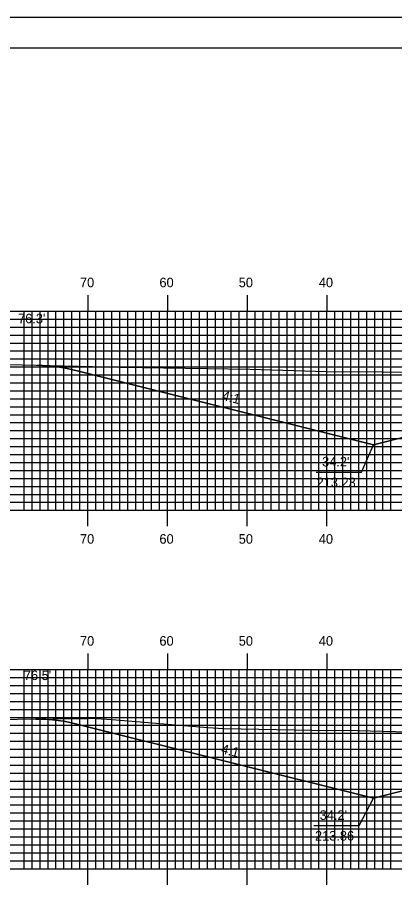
# Model space of a CAD drawing. Extents: x 1820424 to 1820768, y 442591 to 442811.
# Drawn here: x 1820511.4 to 1820558.7, y 442701.2 to 442810.5 of the extents above; entities that cross this region are included whole.
import ezdxf

# ---------------------------------------------------------------- set-up
doc = ezdxf.new("R2010")
doc.units = 0
for name, color, linetype in [('ANNOTATION', 7, 'Continuous'), ('BORDER', 7, 'Continuous'), ('D_Roadway_Centerline', 7, 'Continuous'), ('D_Roadway_SlopeLines', 7, 'Continuous'), ('D_Text_Standard', 7, 'Continuous'), ('H_V ANNOTATION', 7, 'Continuous'), ('MAJOR', 7, 'Continuous'), ('MINOR', 7, 'Continuous'), ('PLOT BOUNDARY', 7, 'Continuous'), ('S_Roadway_Centerline', 7, 'Continuous')]:
    doc.layers.add(name, color=color, linetype=linetype)

msp = doc.modelspace()

# ---------------------------------------------------------------- linework, layer by layer
at = {"layer": 'ANNOTATION'}
for points in [[(1820548.86, 442753.44), (1820554.55, 442753.44), (1820556.03, 442756.9)], [(1820548.55, 442709.08), (1820554.24, 442709.08), (1820556.03, 442712.52)]]:
    msp.add_lwpolyline(points, dxfattribs=at)
at = {"layer": 'BORDER'}
msp.add_lwpolyline([(1820440.6, 442596.67), (1820760.6, 442596.67), (1820760.6, 442806.67), (1820440.6, 442806.67)], close=True, dxfattribs=at)
at = {"layer": 'D_Roadway_Centerline'}
for points in [[(1820513.87, 442766.87), (1820515.12, 442766.81), (1820516.37, 442766.67), (1820517.62, 442766.46), (1820518.87, 442766.19), (1820556.03, 442756.9), (1820560.03, 442757.9), (1820570.2, 442760.44), (1820578.2, 442760.76), (1820590.2, 442761), (1820602.2, 442760.76), (1820612.2, 442760.36), (1820622.2, 442757.86), (1820626.2, 442756.86), (1820654.98, 442764.06), (1820656.23, 442764.33), (1820657.48, 442764.52), (1820658.73, 442764.63), (1820659.98, 442764.66)], [(1820513.66, 442722.46), (1820514.91, 442722.44), (1820516.16, 442722.33), (1820517.41, 442722.14), (1820518.66, 442721.87), (1820556.03, 442712.52), (1820560.03, 442713.52), (1820570.2, 442716.07), (1820578.2, 442716.39), (1820590.2, 442716.63), (1820602.2, 442716.39), (1820612.2, 442715.99), (1820622.2, 442713.49), (1820626.2, 442712.49), (1820652.27, 442719), (1820653.52, 442719.27), (1820654.77, 442719.47), (1820656.02, 442719.58), (1820657.27, 442719.62)]]:
    msp.add_lwpolyline(points, dxfattribs=at)
at = {"layer": 'D_Roadway_SlopeLines'}
for points in [[(1820556.03, 442756.9), (1820518.87, 442766.19), (1820517.62, 442766.46), (1820516.37, 442766.67), (1820515.12, 442766.81), (1820513.87, 442766.87)], [(1820570.2, 442760.44), (1820556.03, 442756.9)], [(1820556.03, 442712.52), (1820518.66, 442721.87), (1820517.41, 442722.14), (1820516.16, 442722.33), (1820514.91, 442722.44), (1820513.66, 442722.46)], [(1820570.2, 442716.07), (1820556.03, 442712.52)]]:
    msp.add_lwpolyline(points, dxfattribs=at)
at = {"layer": 'MAJOR'}
for p, q in [((1820520.2, 442775.67), (1820520.2, 442773.67)), ((1820530.2, 442775.67), (1820530.2, 442773.67)), ((1820540.2, 442775.67), (1820540.2, 442773.67)), ((1820550.2, 442775.67), (1820550.2, 442773.67)), ((1820450.2, 442773.67), (1820730.2, 442773.67)), ((1820450.2, 442773.67), (1820730.2, 442773.67)), ((1820520.2, 442748.67), (1820520.2, 442773.67)), ((1820530.2, 442748.67), (1820530.2, 442773.67)), ((1820540.2, 442748.67), (1820540.2, 442773.67)), ((1820550.2, 442748.67), (1820550.2, 442773.67)), ((1820450.2, 442768.67), (1820730.2, 442768.67)), ((1820450.2, 442763.67), (1820730.2, 442763.67)), ((1820450.2, 442758.67), (1820730.2, 442758.67)), ((1820450.2, 442753.67), (1820730.2, 442753.67)), ((1820450.2, 442748.67), (1820730.2, 442748.67)), ((1820450.2, 442748.67), (1820730.2, 442748.67)), ((1820520.2, 442746.66), (1820520.2, 442748.67)), ((1820530.2, 442746.66), (1820530.2, 442748.67)), ((1820540.2, 442746.66), (1820540.2, 442748.67)), ((1820550.2, 442746.66), (1820550.2, 442748.67)), ((1820520.2, 442730.67), (1820520.2, 442728.67)), ((1820530.2, 442730.67), (1820530.2, 442728.67)), ((1820540.2, 442730.67), (1820540.2, 442728.67)), ((1820550.2, 442730.67), (1820550.2, 442728.67)), ((1820450.2, 442728.67), (1820730.2, 442728.67)), ((1820450.2, 442728.67), (1820730.2, 442728.67)), ((1820520.2, 442703.67), (1820520.2, 442728.67)), ((1820530.2, 442703.67), (1820530.2, 442728.67)), ((1820540.2, 442703.67), (1820540.2, 442728.67)), ((1820550.2, 442703.67), (1820550.2, 442728.67)), ((1820450.2, 442723.67), (1820730.2, 442723.67)), ((1820450.2, 442718.67), (1820730.2, 442718.67)), ((1820450.2, 442713.67), (1820730.2, 442713.67)), ((1820450.2, 442708.67), (1820730.2, 442708.67)), ((1820450.2, 442703.67), (1820730.2, 442703.67)), ((1820450.2, 442703.67), (1820730.2, 442703.67)), ((1820520.2, 442701.66), (1820520.2, 442703.67)), ((1820530.2, 442701.66), (1820530.2, 442703.67)), ((1820540.2, 442701.66), (1820540.2, 442703.67)), ((1820550.2, 442701.66), (1820550.2, 442703.67))]:
    msp.add_line(p, q, dxfattribs=at)
at = {"layer": 'MINOR'}
for p, q in [((1820512.2, 442748.67), (1820512.2, 442773.67)), ((1820513.2, 442748.67), (1820513.2, 442773.67)), ((1820514.2, 442748.67), (1820514.2, 442773.67)), ((1820515.2, 442748.67), (1820515.2, 442773.67)), ((1820516.2, 442748.67), (1820516.2, 442773.67)), ((1820517.2, 442748.67), (1820517.2, 442773.67)), ((1820518.2, 442748.67), (1820518.2, 442773.67)), ((1820519.2, 442748.67), (1820519.2, 442773.67)), ((1820521.2, 442748.67), (1820521.2, 442773.67)), ((1820522.2, 442748.67), (1820522.2, 442773.67)), ((1820523.2, 442748.67), (1820523.2, 442773.67)), ((1820524.2, 442748.67), (1820524.2, 442773.67)), ((1820525.2, 442748.67), (1820525.2, 442773.67)), ((1820526.2, 442748.67), (1820526.2, 442773.67)), ((1820527.2, 442748.67), (1820527.2, 442773.67)), ((1820528.2, 442748.67), (1820528.2, 442773.67)), ((1820529.2, 442748.67), (1820529.2, 442773.67)), ((1820531.2, 442748.67), (1820531.2, 442773.67)), ((1820532.2, 442748.67), (1820532.2, 442773.67)), ((1820533.2, 442748.67), (1820533.2, 442773.67)), ((1820534.2, 442748.67), (1820534.2, 442773.67)), ((1820535.2, 442748.67), (1820535.2, 442773.67)), ((1820536.2, 442748.67), (1820536.2, 442773.67)), ((1820537.2, 442748.67), (1820537.2, 442773.67)), ((1820538.2, 442748.67), (1820538.2, 442773.67)), ((1820539.2, 442748.67), (1820539.2, 442773.67)), ((1820541.2, 442748.67), (1820541.2, 442773.67)), ((1820542.2, 442748.67), (1820542.2, 442773.67)), ((1820543.2, 442748.67), (1820543.2, 442773.67)), ((1820544.2, 442748.67), (1820544.2, 442773.67)), ((1820545.2, 442748.67), (1820545.2, 442773.67)), ((1820546.2, 442748.67), (1820546.2, 442773.67)), ((1820547.2, 442748.67), (1820547.2, 442773.67)), ((1820548.2, 442748.67), (1820548.2, 442773.67)), ((1820549.2, 442748.67), (1820549.2, 442773.67)), ((1820551.2, 442748.67), (1820551.2, 442773.67)), ((1820552.2, 442748.67), (1820552.2, 442773.67)), ((1820553.2, 442748.67), (1820553.2, 442773.67)), ((1820554.2, 442748.67), (1820554.2, 442773.67)), ((1820555.2, 442748.67), (1820555.2, 442773.67)), ((1820556.2, 442748.67), (1820556.2, 442773.67)), ((1820557.2, 442748.67), (1820557.2, 442773.67)), ((1820558.2, 442748.67), (1820558.2, 442773.67)), ((1820450.2, 442772.67), (1820730.2, 442772.67)), ((1820450.2, 442771.67), (1820730.2, 442771.67)), ((1820450.2, 442770.67), (1820730.2, 442770.67)), ((1820450.2, 442769.67), (1820730.2, 442769.67)), ((1820450.2, 442767.67), (1820730.2, 442767.67)), ((1820450.2, 442766.67), (1820730.2, 442766.67)), ((1820450.2, 442765.67), (1820730.2, 442765.67)), ((1820450.2, 442764.67), (1820730.2, 442764.67)), ((1820450.2, 442762.67), (1820730.2, 442762.67)), ((1820450.2, 442761.67), (1820730.2, 442761.67)), ((1820450.2, 442760.67), (1820730.2, 442760.67)), ((1820450.2, 442759.67), (1820730.2, 442759.67)), ((1820450.2, 442757.67), (1820730.2, 442757.67)), ((1820450.2, 442756.67), (1820730.2, 442756.67)), ((1820450.2, 442755.67), (1820730.2, 442755.67)), ((1820450.2, 442754.67), (1820730.2, 442754.67)), ((1820450.2, 442752.67), (1820730.2, 442752.67)), ((1820450.2, 442751.67), (1820730.2, 442751.67)), ((1820450.2, 442750.67), (1820730.2, 442750.67)), ((1820450.2, 442749.67), (1820730.2, 442749.67)), ((1820512.2, 442703.67), (1820512.2, 442728.67)), ((1820513.2, 442703.67), (1820513.2, 442728.67)), ((1820514.2, 442703.67), (1820514.2, 442728.67)), ((1820515.2, 442703.67), (1820515.2, 442728.67)), ((1820516.2, 442703.67), (1820516.2, 442728.67)), ((1820517.2, 442703.67), (1820517.2, 442728.67)), ((1820518.2, 442703.67), (1820518.2, 442728.67)), ((1820519.2, 442703.67), (1820519.2, 442728.67)), ((1820521.2, 442703.67), (1820521.2, 442728.67)), ((1820522.2, 442703.67), (1820522.2, 442728.67)), ((1820523.2, 442703.67), (1820523.2, 442728.67)), ((1820524.2, 442703.67), (1820524.2, 442728.67)), ((1820525.2, 442703.67), (1820525.2, 442728.67)), ((1820526.2, 442703.67), (1820526.2, 442728.67)), ((1820527.2, 442703.67), (1820527.2, 442728.67)), ((1820528.2, 442703.67), (1820528.2, 442728.67)), ((1820529.2, 442703.67), (1820529.2, 442728.67)), ((1820531.2, 442703.67), (1820531.2, 442728.67)), ((1820532.2, 442703.67), (1820532.2, 442728.67)), ((1820533.2, 442703.67), (1820533.2, 442728.67)), ((1820534.2, 442703.67), (1820534.2, 442728.67)), ((1820535.2, 442703.67), (1820535.2, 442728.67)), ((1820536.2, 442703.67), (1820536.2, 442728.67)), ((1820537.2, 442703.67), (1820537.2, 442728.67)), ((1820538.2, 442703.67), (1820538.2, 442728.67)), ((1820539.2, 442703.67), (1820539.2, 442728.67)), ((1820541.2, 442703.67), (1820541.2, 442728.67)), ((1820542.2, 442703.67), (1820542.2, 442728.67)), ((1820543.2, 442703.67), (1820543.2, 442728.67)), ((1820544.2, 442703.67), (1820544.2, 442728.67)), ((1820545.2, 442703.67), (1820545.2, 442728.67)), ((1820546.2, 442703.67), (1820546.2, 442728.67)), ((1820547.2, 442703.67), (1820547.2, 442728.67)), ((1820548.2, 442703.67), (1820548.2, 442728.67)), ((1820549.2, 442703.67), (1820549.2, 442728.67)), ((1820551.2, 442703.67), (1820551.2, 442728.67)), ((1820552.2, 442703.67), (1820552.2, 442728.67)), ((1820553.2, 442703.67), (1820553.2, 442728.67)), ((1820554.2, 442703.67), (1820554.2, 442728.67)), ((1820555.2, 442703.67), (1820555.2, 442728.67)), ((1820556.2, 442703.67), (1820556.2, 442728.67)), ((1820557.2, 442703.67), (1820557.2, 442728.67)), ((1820558.2, 442703.67), (1820558.2, 442728.67)), ((1820450.2, 442727.67), (1820730.2, 442727.67)), ((1820450.2, 442726.67), (1820730.2, 442726.67)), ((1820450.2, 442725.67), (1820730.2, 442725.67)), ((1820450.2, 442724.67), (1820730.2, 442724.67)), ((1820450.2, 442722.67), (1820730.2, 442722.67)), ((1820450.2, 442721.67), (1820730.2, 442721.67)), ((1820450.2, 442720.67), (1820730.2, 442720.67)), ((1820450.2, 442719.67), (1820730.2, 442719.67)), ((1820450.2, 442717.67), (1820730.2, 442717.67)), ((1820450.2, 442716.67), (1820730.2, 442716.67)), ((1820450.2, 442715.67), (1820730.2, 442715.67)), ((1820450.2, 442714.67), (1820730.2, 442714.67)), ((1820450.2, 442712.67), (1820730.2, 442712.67)), ((1820450.2, 442711.67), (1820730.2, 442711.67)), ((1820450.2, 442710.67), (1820730.2, 442710.67)), ((1820450.2, 442709.67), (1820730.2, 442709.67)), ((1820450.2, 442707.67), (1820730.2, 442707.67)), ((1820450.2, 442706.67), (1820730.2, 442706.67)), ((1820450.2, 442705.67), (1820730.2, 442705.67)), ((1820450.2, 442704.67), (1820730.2, 442704.67))]:
    msp.add_line(p, q, dxfattribs=at)
at = {"layer": 'PLOT BOUNDARY'}
msp.add_lwpolyline([(1820424.42, 442590.55), (1820764.42, 442590.55), (1820764.42, 442810.55), (1820424.42, 442810.55)], close=True, dxfattribs=at)
at = {"layer": 'S_Roadway_Centerline'}
for points in [[(1820450.2, 442767.88), (1820454.43, 442767.81), (1820456.57, 442767.78), (1820461.62, 442767.61), (1820472.98, 442767.23), (1820483.25, 442767.34), (1820489.5, 442767.31), (1820500.41, 442767.14), (1820506.6, 442767.04), (1820524.28, 442766.63), (1820540.55, 442766.4), (1820550.14, 442766.1), (1820557.24, 442766.04), (1820570.2, 442765.82), (1820575.02, 442765.8), (1820589.12, 442765.34), (1820606.04, 442764.82), (1820615.95, 442764.71), (1820625.49, 442764.7), (1820631.43, 442764.99), (1820642, 442765.07), (1820655.12, 442764.74)], [(1820502.48, 442722.35), (1820520.29, 442722.53), (1820520.93, 442722.55), (1820521.25, 442722.54), (1820523.25, 442722.38), (1820535.25, 442721.39), (1820537.21, 442721.26), (1820548.29, 442721.07), (1820554.03, 442721), (1820563.61, 442720.77), (1820570.69, 442720.52), (1820586.74, 442720.2), (1820587.5, 442720.18), (1820587.95, 442720.18), (1820589.81, 442720.13), (1820615.47, 442719.64), (1820621.46, 442719.6), (1820627.75, 442719.67), (1820654.9, 442719.63)]]:
    msp.add_lwpolyline(points, dxfattribs=at)

# ---------------------------------------------------------------- texts
at = {"layer": 'ANNOTATION'}
for p in [(1820536.96, 442762.53), (1820536.85, 442718.18)]:
    msp.add_text('4:1', height=1.2, rotation=345.9638, dxfattribs=at).set_placement(p)
for s, p in [("34.2'", (1820549.59, 442754.17)), ('213.23', (1820548.9, 442751.57)), ("34.2'", (1820549.29, 442709.8)), ('213.86', (1820548.7, 442707.2))]:
    msp.add_text(s, height=1.2, dxfattribs=at).set_placement(p)
at = {"layer": 'D_Text_Standard'}
for s, p in [("76.3'", (1820511.44, 442772.14)), ("76.5'", (1820512.17, 442727.35))]:
    msp.add_text(s, height=1.2, dxfattribs=at).set_placement(p)
at = {"layer": 'H_V ANNOTATION'}
for s, p in [('70', (1820519.21, 442776.67)), ('60', (1820529.18, 442776.67)), ('50', (1820539.13, 442776.67)), ('40', (1820549.18, 442776.67)), ('70', (1820519.21, 442744.47)), ('60', (1820529.18, 442744.47)), ('50', (1820539.13, 442744.47)), ('40', (1820549.18, 442744.47)), ('70', (1820519.21, 442731.67)), ('60', (1820529.18, 442731.67)), ('50', (1820539.13, 442731.67)), ('40', (1820549.18, 442731.67))]:
    msp.add_text(s, height=1.2, dxfattribs=at).set_placement(p)

doc.saveas('drawing.dxf')
